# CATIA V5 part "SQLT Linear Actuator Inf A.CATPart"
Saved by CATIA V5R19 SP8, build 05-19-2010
Part number: SQLT Linear Actuator Inf A
Publications: "Droite.1", "Plan.1", "Droite.2"
Bounding box of the stored display mesh (mm): x -150 to 150, y 10 to 410, z 620 to 620
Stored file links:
  G:\EU_thinkMotion\CFAO_2010\MMS_groupe3\MMS_groupe3\A reprendre\fovide\fovide\SQLT Linear Actuator Inf A.CATPart
  G:\EU_thinkMotion\CFAO_2010\MMS_groupe3\MMS_groupe3\A reprendre\fovide\fovide\fovide.CATProduct
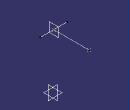
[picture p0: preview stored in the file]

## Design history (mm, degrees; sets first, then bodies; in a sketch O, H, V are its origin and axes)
Set1
  Point1 "Point.N": linked copy from another document
  Point2 "Point.O": linked copy from another document
Set2 "set SQLT Linear Actuator Inf A"
  Line1: type PtPt, FirstPoint Point1, SecondPoint Point2
  Plane1: type OffsetPt, RefPlane yz-plane, RefPoint Point2
  Line2: type Normal, RefPoint Point2, RefSkin Plane1, Start -150, End 150
Body1 (main body)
